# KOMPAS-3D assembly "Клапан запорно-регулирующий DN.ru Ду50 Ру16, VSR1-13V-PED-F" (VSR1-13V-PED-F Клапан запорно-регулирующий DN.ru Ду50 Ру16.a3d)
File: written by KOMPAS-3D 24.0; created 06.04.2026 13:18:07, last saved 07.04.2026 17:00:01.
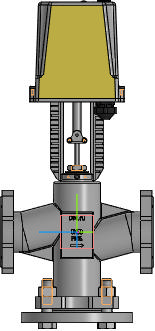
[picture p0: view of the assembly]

Document properties: Автор: R2D2; Полное имя файла: E:\Работа\Зайцев\Солянка\VSR1-13V-PED-F Клапан запорно-регулирующий DN.ru\DN50\исходные материалы\VSR1-13V-PED-F Клапан запорно-регулирующий DN.ru Ду50 Ру16.a3d

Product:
- Component [detail]: Фланец  | qty 2  | pos. 1  | Масса: 1.756734; Автор: R2D2; source file: Фланец.m3d
- Component [detail]: Фланец  | qty 1  | pos. 2  | Масса: 1.756734; Автор: R2D2; source file: Фланец.m3d
- Component [detail]: Корпус  | qty 1  | pos. 3  | Масса: 6.9; Автор: R2D2; source file: Корпус.m3d
- Component [detail]: Электропривод  | qty 1  | pos. 6  | Масса: 0.101125; Автор: R2D2; source file: Электропривод.m3d
- Component [standard]: Болт с шестигранной головкой ГОСТ Р ИСО 4014 - М16 x 65  | qty 4  | Материал: Не определено (density 1000 kg/m3); Масса: 0.1404; Раздел спецификации: Стандартные изделия; Рассекать на разрезах: no; additional columns: ГОСТ Р ИСО 4014-2013
- Component [standard]: Гайка М16-6H ГОСТ 5915-70  | qty 4  | Масса: 0.03761; Раздел спецификации: Стандартные изделия; Рассекать на разрезах: no; additional columns: М1,6-6H
- Part/product: Клапан запорно-регулирующий DN.ru Ду50 Ру16  | designation VSR1-13V-PED-F
    Масса: 13.7
    Раздел спецификации: Прочие изделия
    Примечание: D090-02891

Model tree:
1. Эскиз:1
2. Ось конической поверхности:19
3. Смещенная плоскость:19
4. ЛСК:19  (with: Плоскость XY, Плоскость ZX, Плоскость ZY, Ось X, Ось Y, Ось Z)
     Ось X. Y = -1; Ось Y. X = 1; Ось Z. Z = 1; Точка начала. Х = 44.1942; Точка начала. Y = -135; Точка начала. Z = 44.1942
5. Болтовое соединение
6. Массив по концентрической сетке:3  (with: Грань.Элемент выдавливания:1, Грань.Элемент вращения:1, Грань.Элемент выдавливания:8)  (4 pattern instances)
     Шаг 2 = 360; Ориентация = 2; Расстояние = -38

Expressions: VSR1-13V-PED-F; -L/2
Referenced files in E:\Работа\Зайцев\Солянка\VSR1-13V-PED-F Клапан запорно-регулирующий DN.ru\DN50\исходные материалы\: Фланец.m3d, Корпус.m3d, Электропривод.m3d
Referenced files in C:\Program Files\ASCON\KOMPAS-3D v24\Libs\PolynomLib\DATA\vault\Methods\Kompas\3D\: PLib_Bolt_1_ISO_1100.m3d, PLib_Nut_OST92_900.m3d
Referenced files in E:\Работа\Зайцев\Солянка\VSR1-13V-PED-F Клапан запорно-регулирующий DN.ru\DN20\исходные материалы\: Фланец.m3d
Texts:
  Болт с шестигранной головкой
  Крепежное изделие ГОСТ
  Программные изделия  и базы данных
  Edge1
  Edge2
  TKR3D
  Справочник стандартных изделий
  Фланец (1)
  Фланец (2)
  Фланец (3)
  Болт с шестигранной головкой ГОСТ Р ИСО 4014 - М16 x 65 (1)
  hole1
  hole2
  Гайка М16-6H ГОСТ 5915-70 (1)
  bcut1
  hcut1
  cut1
  Плоскость XY.Начало координат
  Ось Z.Начало координат
  Плоскость ZY.Начало координат
  Плоскость ZX.Начало координат
  Ось Y.Начало координат
  Plane. Начало координат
